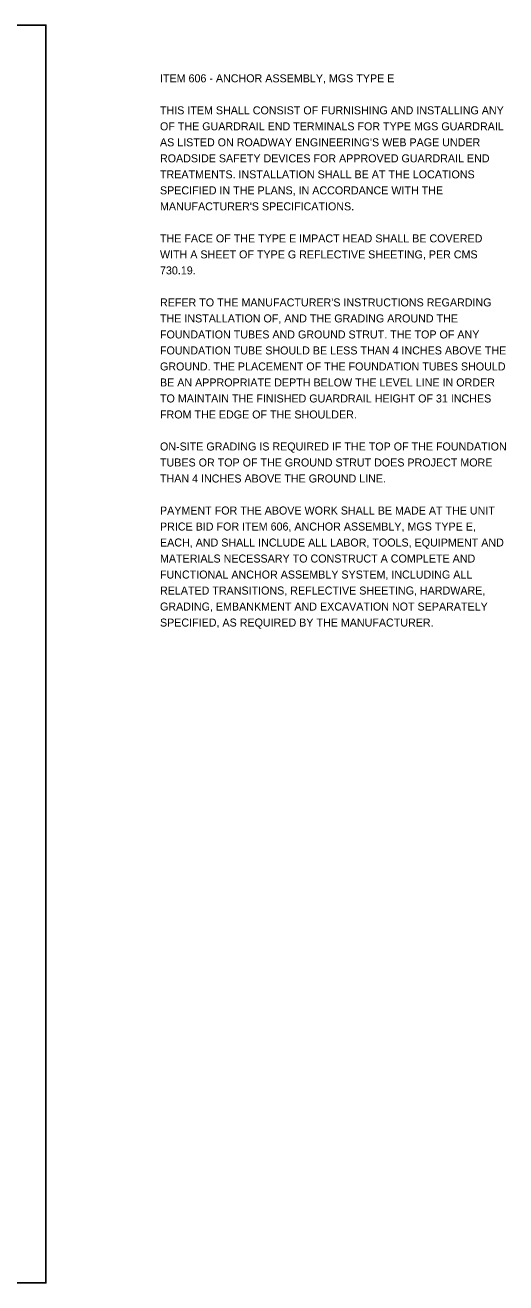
# Model space of a CAD drawing. Extents: x -7.4 to 42, y 0 to 22.
# Drawn here: x 33.64 to 42.04, y 0 to 22 of the extents above; entities that cross this region are included whole.
import ezdxf

# ---------------------------------------------------------------- set-up
doc = ezdxf.new("R2010")
doc.units = 0
doc.layers.add('SH_Data', color=7, linetype='Continuous')
doc.layers.add('SH_Text', color=7, linetype='Continuous')

msp = doc.modelspace()

# ---------------------------------------------------------------- linework, layer by layer
at = {"layer": 'SH_Data'}
msp.add_lwpolyline([(0, 0), (34, 0), (34, 22), (0, 22)], close=True, dxfattribs=at)

# ---------------------------------------------------------------- texts
at = {"layer": 'SH_Text'}
for s, p in [('ITEM 606 - ANCHOR ASSEMBLY, MGS TYPE E', (35.996, 21)), ('THIS ITEM SHALL CONSIST OF FURNISHING AND INSTALLING ANY', (35.996, 20.44)), ('OF THE GUARDRAIL END TERMINALS FOR TYPE MGS GUARDRAIL', (35.996, 20.16)), ("AS LISTED ON ROADWAY ENGINEERING'S WEB PAGE UNDER", (35.996, 19.88)), ('ROADSIDE SAFETY DEVICES FOR APPROVED GUARDRAIL END', (35.996, 19.6)), ('TREATMENTS. INSTALLATION SHALL BE AT THE LOCATIONS', (35.996, 19.32)), ('SPECIFIED IN THE PLANS, IN ACCORDANCE WITH THE', (35.996, 19.04)), ("MANUFACTURER'S SPECIFICATIONS.", (35.996, 18.76)), ('THE FACE OF THE TYPE E IMPACT HEAD SHALL BE COVERED', (35.996, 18.2)), ('WITH A SHEET OF TYPE G REFLECTIVE SHEETING, PER CMS', (35.996, 17.92)), ('730.19.', (35.996, 17.64)), ("REFER TO THE MANUFACTURER'S INSTRUCTIONS REGARDING", (35.996, 17.08)), ('THE INSTALLATION OF, AND THE GRADING AROUND THE', (35.996, 16.8)), ('FOUNDATION TUBES AND GROUND STRUT. THE TOP OF ANY', (35.996, 16.52)), ('FOUNDATION TUBE SHOULD BE LESS THAN 4 INCHES ABOVE THE', (35.996, 16.24)), ('GROUND. THE PLACEMENT OF THE FOUNDATION TUBES SHOULD', (35.996, 15.96)), ('BE AN APPROPRIATE DEPTH BELOW THE LEVEL LINE IN ORDER', (35.996, 15.68)), ('TO MAINTAIN THE FINISHED GUARDRAIL HEIGHT OF 31 INCHES', (35.996, 15.4)), ('FROM THE EDGE OF THE SHOULDER.', (35.996, 15.12)), ('ON-SITE GRADING IS REQUIRED IF THE TOP OF THE FOUNDATION', (35.996, 14.56)), ('TUBES OR TOP OF THE GROUND STRUT DOES PROJECT MORE', (35.996, 14.28)), ('THAN 4 INCHES ABOVE THE GROUND LINE.', (35.996, 14)), ('PAYMENT FOR THE ABOVE WORK SHALL BE MADE AT THE UNIT', (35.996, 13.44)), ('PRICE BID FOR ITEM 606, ANCHOR ASSEMBLY, MGS TYPE E,', (35.996, 13.16)), ('EACH, AND SHALL INCLUDE ALL LABOR, TOOLS, EQUIPMENT AND', (35.996, 12.88)), ('MATERIALS NECESSARY TO CONSTRUCT A COMPLETE AND', (35.996, 12.6)), ('FUNCTIONAL ANCHOR ASSEMBLY SYSTEM, INCLUDING ALL', (35.996, 12.32)), ('RELATED TRANSITIONS, REFLECTIVE SHEETING, HARDWARE,', (35.996, 12.04)), ('GRADING, EMBANKMENT AND EXCAVATION NOT SEPARATELY', (35.996, 11.76)), ('SPECIFIED, AS REQUIRED BY THE MANUFACTURER.', (35.996, 11.48))]:
    msp.add_text(s, height=0.14, dxfattribs=at).set_placement(p)

doc.saveas('drawing.dxf')
